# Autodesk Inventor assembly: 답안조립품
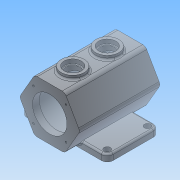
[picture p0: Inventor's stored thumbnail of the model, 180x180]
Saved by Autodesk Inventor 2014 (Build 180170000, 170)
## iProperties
Created: 2021-06
Part Number: 답안조립품
Document SubType Name: Assembly
Designer: net
Author: net
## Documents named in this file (2)
- C:\Users\net\Desktop\710606V1002\답안조립품.iam
- C:\Users\net\Documents\Inventor\710606V1002\답안부품.ipt
